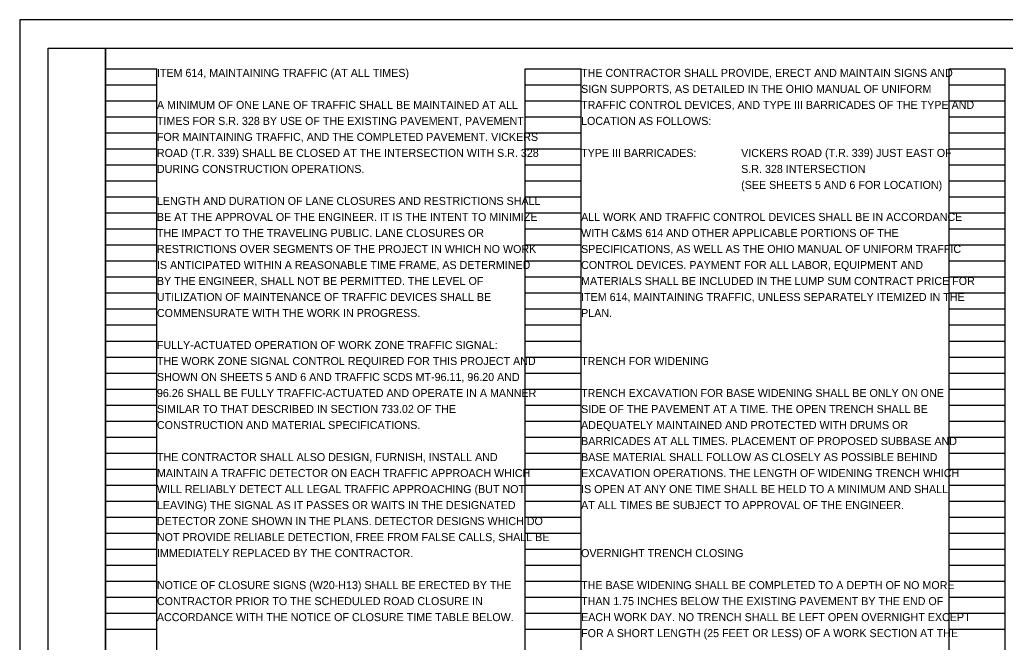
# Model space of a CAD drawing. Extents: x 0 to 74, y -29.1 to 22.
# Drawn here: x 0 to 17.24, y 11.11 to 22 of the extents above; entities that cross this region are included whole.
import ezdxf

# ---------------------------------------------------------------- set-up
doc = ezdxf.new("R2010")
doc.units = 0
for name, color, linetype in [('SH_Border', 7, 'Continuous'), ('SH_Cut_Line', 7, 'Continuous'), ('SH_Data', 7, 'Continuous'), ('SH_Text', 7, 'Continuous')]:
    doc.layers.add(name, color=color, linetype=linetype)

msp = doc.modelspace()

# ---------------------------------------------------------------- linework, layer by layer
at = {"layer": 'SH_Border'}
for points in [[(0.5, 21.5), (1.5, 21.5), (1.5, 0.5), (0.5, 0.5)], [(1.5, 21.5), (33.5, 21.5), (33.5, 0.5), (1.5, 0.5)]]:
    msp.add_lwpolyline(points, close=True, dxfattribs=at)
at = {"layer": 'SH_Cut_Line'}
msp.add_lwpolyline([(0, 0), (34, 0), (34, 22), (0, 22)], close=True, dxfattribs=at)
at = {"layer": 'SH_Data'}
for p, q in [((1.5, 0.98), (1.5, 21.14)), ((1.5, 21.14), (2.4, 21.14)), ((2.4, 0.98), (2.4, 21.14)), ((8.84, 0.98), (8.84, 21.14)), ((8.84, 21.14), (9.82, 21.14)), ((9.82, 0.98), (9.82, 21.14)), ((16.26, 0.98), (16.26, 21.14)), ((16.26, 21.14), (17.24, 21.14)), ((17.24, 0.98), (17.24, 21.14)), ((1.5, 20.86), (2.4, 20.86)), ((8.84, 20.86), (9.82, 20.86)), ((16.26, 20.86), (17.24, 20.86)), ((1.5, 20.58), (2.4, 20.58)), ((8.84, 20.58), (9.82, 20.58)), ((16.26, 20.58), (17.24, 20.58)), ((1.5, 20.3), (2.4, 20.3)), ((8.84, 20.3), (9.82, 20.3)), ((16.26, 20.3), (17.24, 20.3)), ((1.5, 20.02), (2.4, 20.02)), ((8.84, 20.02), (9.82, 20.02)), ((16.26, 20.02), (17.24, 20.02)), ((1.5, 19.74), (2.4, 19.74)), ((8.84, 19.74), (9.82, 19.74)), ((16.26, 19.74), (17.24, 19.74)), ((1.5, 19.46), (2.4, 19.46)), ((8.84, 19.46), (9.82, 19.46)), ((16.26, 19.46), (17.24, 19.46)), ((1.5, 19.18), (2.4, 19.18)), ((8.84, 19.18), (9.82, 19.18)), ((16.26, 19.18), (17.24, 19.18)), ((1.5, 18.9), (2.4, 18.9)), ((8.84, 18.9), (9.82, 18.9)), ((16.26, 18.9), (17.24, 18.9)), ((1.5, 18.62), (2.4, 18.62)), ((8.84, 18.62), (9.82, 18.62)), ((16.26, 18.62), (17.24, 18.62)), ((1.5, 18.34), (2.4, 18.34)), ((8.84, 18.34), (9.82, 18.34)), ((16.26, 18.34), (17.24, 18.34)), ((1.5, 18.06), (2.4, 18.06)), ((8.84, 18.06), (9.82, 18.06)), ((16.26, 18.06), (17.24, 18.06)), ((1.5, 17.78), (2.4, 17.78)), ((8.84, 17.78), (9.82, 17.78)), ((16.26, 17.78), (17.24, 17.78)), ((1.5, 17.5), (2.4, 17.5)), ((8.84, 17.5), (9.82, 17.5)), ((16.26, 17.5), (17.24, 17.5)), ((1.5, 17.22), (2.4, 17.22)), ((8.84, 17.22), (9.82, 17.22)), ((16.26, 17.22), (17.24, 17.22)), ((1.5, 16.94), (2.4, 16.94)), ((8.84, 16.94), (9.82, 16.94)), ((16.26, 16.94), (17.24, 16.94)), ((1.5, 16.66), (2.4, 16.66)), ((8.84, 16.66), (9.82, 16.66)), ((16.26, 16.66), (17.24, 16.66)), ((1.5, 16.38), (2.4, 16.38)), ((8.84, 16.38), (9.82, 16.38)), ((16.26, 16.38), (17.24, 16.38)), ((1.5, 16.1), (2.4, 16.1)), ((8.84, 16.1), (9.82, 16.1)), ((16.26, 16.1), (17.24, 16.1)), ((1.5, 15.82), (2.4, 15.82)), ((8.84, 15.82), (9.82, 15.82)), ((16.26, 15.82), (17.24, 15.82)), ((1.5, 15.54), (2.4, 15.54)), ((8.84, 15.54), (9.82, 15.54)), ((16.26, 15.54), (17.24, 15.54)), ((1.5, 15.26), (2.4, 15.26)), ((8.84, 15.26), (9.82, 15.26)), ((16.26, 15.26), (17.24, 15.26)), ((1.5, 14.98), (2.4, 14.98)), ((8.84, 14.98), (9.82, 14.98)), ((16.26, 14.98), (17.24, 14.98)), ((1.5, 14.7), (2.4, 14.7)), ((8.84, 14.7), (9.82, 14.7)), ((16.26, 14.7), (17.24, 14.7)), ((1.5, 14.42), (2.4, 14.42)), ((8.84, 14.42), (9.82, 14.42)), ((16.26, 14.42), (17.24, 14.42)), ((1.5, 14.14), (2.4, 14.14)), ((8.84, 14.14), (9.82, 14.14)), ((16.26, 14.14), (17.24, 14.14)), ((1.5, 13.86), (2.4, 13.86)), ((8.84, 13.86), (9.82, 13.86)), ((16.26, 13.86), (17.24, 13.86)), ((1.5, 13.58), (2.4, 13.58)), ((8.84, 13.58), (9.82, 13.58)), ((16.26, 13.58), (17.24, 13.58)), ((1.5, 13.3), (2.4, 13.3)), ((8.84, 13.3), (9.82, 13.3)), ((16.26, 13.3), (17.24, 13.3)), ((1.5, 13.02), (2.4, 13.02)), ((8.84, 13.02), (9.82, 13.02)), ((16.26, 13.02), (17.24, 13.02)), ((1.5, 12.74), (2.4, 12.74)), ((8.84, 12.74), (9.82, 12.74)), ((16.26, 12.74), (17.24, 12.74)), ((1.5, 12.46), (2.4, 12.46)), ((8.84, 12.46), (9.82, 12.46)), ((16.26, 12.46), (17.24, 12.46)), ((1.5, 12.18), (2.4, 12.18)), ((8.84, 12.18), (9.82, 12.18)), ((16.26, 12.18), (17.24, 12.18)), ((1.5, 11.9), (2.4, 11.9)), ((8.84, 11.9), (9.82, 11.9)), ((16.26, 11.9), (17.24, 11.9)), ((1.5, 11.62), (2.4, 11.62)), ((8.84, 11.62), (9.82, 11.62)), ((16.26, 11.62), (17.24, 11.62)), ((1.5, 11.34), (2.4, 11.34)), ((8.84, 11.34), (9.82, 11.34)), ((16.26, 11.34), (17.24, 11.34))]:
    msp.add_line(p, q, dxfattribs=at)

# ---------------------------------------------------------------- texts
at = {"layer": 'SH_Text'}
for s, p in [('ITEM 614, MAINTAINING TRAFFIC (AT ALL TIMES)', (2.4, 21)), ('THE CONTRACTOR SHALL PROVIDE, ERECT AND MAINTAIN SIGNS AND ', (9.82, 21)), ('SIGN SUPPORTS, AS DETAILED IN THE OHIO MANUAL OF UNIFORM ', (9.82, 20.72)), ('A MINIMUM OF ONE LANE OF TRAFFIC SHALL BE MAINTAINED AT ALL ', (2.4, 20.44)), ('TRAFFIC CONTROL DEVICES, AND TYPE III BARRICADES OF THE TYPE AND ', (9.82, 20.44)), ('TIMES FOR S.R. 328 BY USE OF THE EXISTING PAVEMENT, PAVEMENT ', (2.4, 20.16)), ('LOCATION AS FOLLOWS:', (9.82, 20.16)), ('FOR MAINTAINING TRAFFIC, AND THE COMPLETED PAVEMENT. VICKERS ', (2.4, 19.88)), ('ROAD (T.R. 339) SHALL BE CLOSED AT THE INTERSECTION WITH S.R. 328 ', (2.4, 19.6)), ('TYPE III BARRICADES:', (9.82, 19.6)), ('VICKERS ROAD (T.R. 339) JUST EAST OF ', (12.62, 19.6)), ('DURING CONSTRUCTION OPERATIONS.', (2.4, 19.32)), ('S.R. 328 INTERSECTION', (12.62, 19.32)), ('(SEE SHEETS 5 AND 6 FOR LOCATION)', (12.62, 19.04)), ('LENGTH AND DURATION OF LANE CLOSURES AND RESTRICTIONS SHALL ', (2.4, 18.76)), ('BE AT THE APPROVAL OF THE ENGINEER. IT IS THE INTENT TO MINIMIZE ', (2.4, 18.48)), ('ALL WORK AND TRAFFIC CONTROL DEVICES SHALL BE IN ACCORDANCE ', (9.82, 18.48)), ('THE IMPACT TO THE TRAVELING PUBLIC. LANE CLOSURES OR ', (2.4, 18.2)), ('WITH C&MS 614 AND OTHER APPLICABLE PORTIONS OF THE ', (9.82, 18.2)), ('RESTRICTIONS OVER SEGMENTS OF THE PROJECT IN WHICH NO WORK ', (2.4, 17.92)), ('SPECIFICATIONS, AS WELL AS THE OHIO MANUAL OF UNIFORM TRAFFIC ', (9.82, 17.92)), ('IS ANTICIPATED WITHIN A REASONABLE TIME FRAME, AS DETERMINED ', (2.4, 17.64)), ('CONTROL DEVICES. PAYMENT FOR ALL LABOR, EQUIPMENT AND ', (9.82, 17.64)), ('BY THE ENGINEER, SHALL NOT BE PERMITTED. THE LEVEL OF ', (2.4, 17.36)), ('MATERIALS SHALL BE INCLUDED IN THE LUMP SUM CONTRACT PRICE FOR ', (9.82, 17.36)), ('UTILIZATION OF MAINTENANCE OF TRAFFIC DEVICES SHALL BE ', (2.4, 17.08)), ('ITEM 614, MAINTAINING TRAFFIC, UNLESS SEPARATELY ITEMIZED IN THE ', (9.82, 17.08)), ('COMMENSURATE WITH THE WORK IN PROGRESS.', (2.4, 16.8)), ('PLAN.', (9.82, 16.8)), ('FULLY-ACTUATED OPERATION OF WORK ZONE TRAFFIC SIGNAL:', (2.4, 16.24)), ('THE WORK ZONE SIGNAL CONTROL REQUIRED FOR THIS PROJECT AND ', (2.4, 15.96)), ('TRENCH FOR WIDENING', (9.82, 15.96)), ('SHOWN ON SHEETS 5 AND 6 AND TRAFFIC SCDS MT-96.11, 96.20 AND ', (2.4, 15.68)), ('96.26 SHALL BE FULLY TRAFFIC-ACTUATED AND OPERATE IN A MANNER ', (2.4, 15.4)), ('TRENCH EXCAVATION FOR BASE WIDENING SHALL BE ONLY ON ONE ', (9.82, 15.4)), ('SIMILAR TO THAT DESCRIBED IN SECTION 733.02 OF THE ', (2.4, 15.12)), ('SIDE OF THE PAVEMENT AT A TIME. THE OPEN TRENCH SHALL BE ', (9.82, 15.12)), ('CONSTRUCTION AND MATERIAL SPECIFICATIONS.', (2.4, 14.84)), ('ADEQUATELY MAINTAINED AND PROTECTED WITH DRUMS OR ', (9.82, 14.84)), ('BARRICADES AT ALL TIMES. PLACEMENT OF PROPOSED SUBBASE AND ', (9.82, 14.56)), ('THE CONTRACTOR SHALL ALSO DESIGN, FURNISH, INSTALL AND ', (2.4, 14.28)), ('BASE MATERIAL SHALL FOLLOW AS CLOSELY AS POSSIBLE BEHIND ', (9.82, 14.28)), ('MAINTAIN A TRAFFIC DETECTOR ON EACH TRAFFIC APPROACH WHICH ', (2.4, 14)), ('EXCAVATION OPERATIONS. THE LENGTH OF WIDENING TRENCH WHICH ', (9.82, 14)), ('WILL RELIABLY DETECT ALL LEGAL TRAFFIC APPROACHING (BUT NOT ', (2.4, 13.72)), ('IS OPEN AT ANY ONE TIME SHALL BE HELD TO A MINIMUM AND SHALL ', (9.82, 13.72)), ('LEAVING) THE SIGNAL AS IT PASSES OR WAITS IN THE DESIGNATED ', (2.4, 13.44)), ('AT ALL TIMES BE SUBJECT TO APPROVAL OF THE ENGINEER.', (9.82, 13.44)), ('DETECTOR ZONE SHOWN IN THE PLANS. DETECTOR DESIGNS WHICH DO ', (2.4, 13.16)), ('NOT PROVIDE RELIABLE DETECTION, FREE FROM FALSE CALLS, SHALL BE ', (2.4, 12.88)), ('IMMEDIATELY REPLACED BY THE CONTRACTOR.', (2.4, 12.6)), ('OVERNIGHT TRENCH CLOSING', (9.82, 12.6)), ('NOTICE OF CLOSURE SIGNS (W20-H13) SHALL BE ERECTED BY THE ', (2.4, 12.04)), ('THE BASE WIDENING SHALL BE COMPLETED TO A DEPTH OF NO MORE ', (9.82, 12.04)), ('CONTRACTOR PRIOR TO THE SCHEDULED ROAD CLOSURE IN ', (2.4, 11.76)), ('THAN 1.75 INCHES BELOW THE EXISTING PAVEMENT BY THE END OF ', (9.82, 11.76)), ('ACCORDANCE WITH THE NOTICE OF CLOSURE TIME TABLE BELOW. ', (2.4, 11.48)), ('EACH WORK DAY. NO TRENCH SHALL BE LEFT OPEN OVERNIGHT EXCEPT ', (9.82, 11.48)), ('FOR A SHORT LENGTH (25 FEET OR LESS) OF A WORK SECTION AT THE ', (9.82, 11.2))]:
    msp.add_text(s, height=0.14, dxfattribs=at).set_placement(p)

doc.saveas('drawing.dxf')
